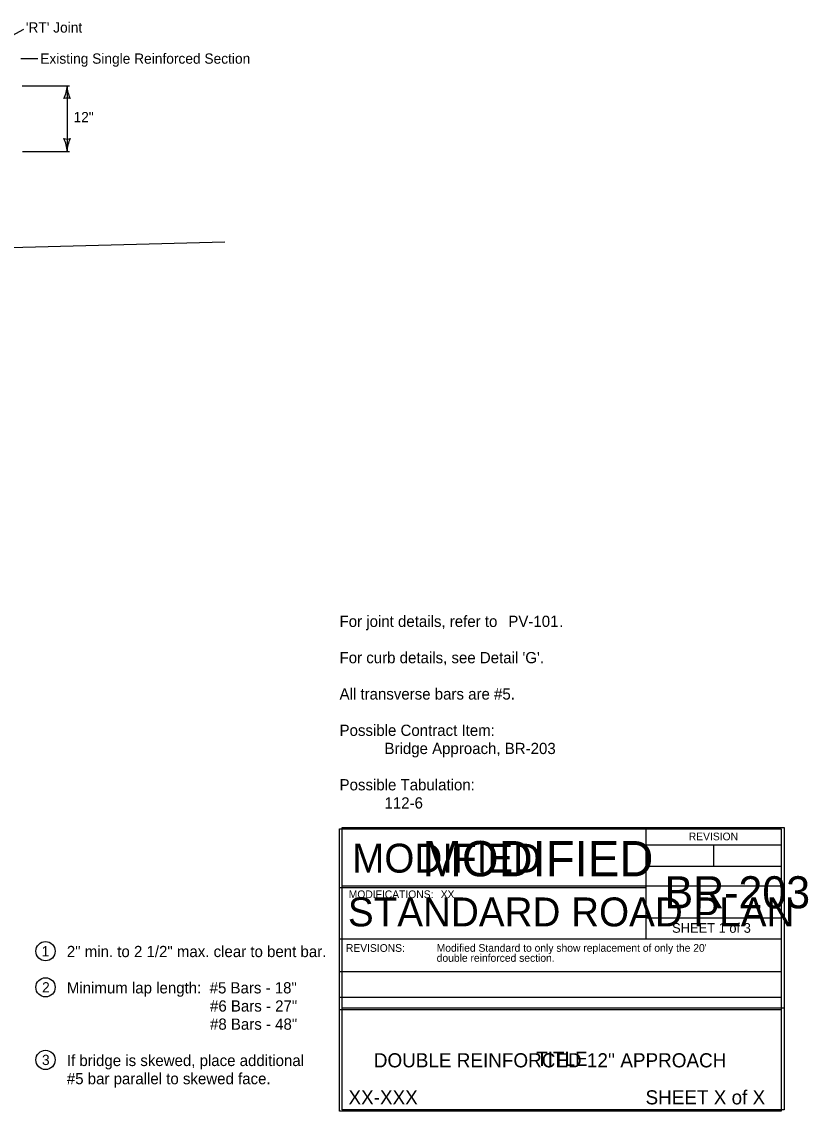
# Model space of a CAD drawing. Extents: x -2135039 to -2124495, y -2139046 to -2132546.
# Drawn here: x -2132982 to -2131757, y -2139046 to -2137348 of the extents above; entities that cross this region are included whole.
import ezdxf

# ---------------------------------------------------------------- set-up
doc = ezdxf.new("R2010")
doc.units = 0
for name, color, linetype in [('Barrier', 7, 'Continuous'), ('BridgeSuperStructureExisting', 7, 'Continuous'), ('Dimension', 7, 'Continuous'), ('dsnAlignmentCurveData', 7, 'Continuous'), ('dsnAlignmentTic', 7, 'Continuous'), ('DsnShtInsideBorder', 7, 'Continuous'), ('dsnStdLabel', 7, 'Continuous')]:
    doc.layers.add(name, color=color, linetype=linetype)

msp = doc.modelspace()

# ---------------------------------------------------------------- linework, layer by layer
at = {"layer": 'BridgeSuperStructureExisting'}
msp.add_line((-2132957.5, -2137405.9), (-2132984.1, -2137405.9), dxfattribs=at)
for centre in [(-2132945.4, -2138796.6), (-2132945.4, -2138852.9), (-2132945.4, -2138966)]:
    msp.add_circle(centre, 15, dxfattribs=at)
for centre, radius, start, end in [((-2132954.3, -2137448), 42.5, 331.9275, 360), ((-2132954.3, -2137448), 42.5, 331.9275, 360), ((-2132869.3, -2137448), 42.5, 180, 208.0725), ((-2132869.3, -2137448), 42.5, 180, 208.0725), ((-2132911.8, -2137483.6), 16.4, 72.2666, 107.7334), ((-2132911.8, -2137483.6), 16.4, 72.2666, 107.7334), ((-2132911.8, -2137514.7), 16.4, 252.2666, 287.7333), ((-2132954.3, -2137550.3), 42.5, 360, 28.0725), ((-2132869.3, -2137550.3), 42.5, 151.9275, 180)]:
    msp.add_arc(centre, radius, start, end, dxfattribs=at)
at = {"layer": 'Dimension'}
for p, q in [((-2132010.4, -2138605.9), (-2132010.4, -2138697.3)), ((-2132010.4, -2138630.9), (-2131799.4, -2138630.9)), ((-2131904.9, -2138630.9), (-2131904.9, -2138664.1)), ((-2132010.4, -2138664.1), (-2131799.4, -2138664.1)), ((-2132487.5, -2138697.3), (-2132010.4, -2138697.3)), ((-2132010.4, -2138697.3), (-2132010.4, -2138777.3)), ((-2131799.4, -2138745.1), (-2132010.4, -2138745.1)), ((-2132487.5, -2138777.3), (-2131799.4, -2138777.3)), ((-2132487.5, -2138828.3), (-2131799.4, -2138828.3)), ((-2132487.5, -2138868.3), (-2131799.4, -2138868.3)), ((-2132487.5, -2138887.3), (-2131799.4, -2138887.3))]:
    msp.add_line(p, q, dxfattribs=at)
msp.add_lwpolyline([(-2132487.5, -2138605.9), (-2131799.4, -2138605.9), (-2131799.4, -2139045.9), (-2132487.5, -2139045.9)], close=True, dxfattribs=at)
at = {"layer": 'DsnShtInsideBorder'}
for p, q in [((-2132483.1, -2138695), (-2131795.1, -2138695)), ((-2132483.1, -2138885), (-2131795.1, -2138885))]:
    msp.add_line(p, q, dxfattribs=at)
msp.add_lwpolyline([(-2132483.1, -2138603.7), (-2131795.1, -2138603.7), (-2131795.1, -2139043.7), (-2132483.1, -2139043.7)], close=True, dxfattribs=at)
at = {"layer": 'dsnStdLabel'}
for p, q in [((-2133142.6, -2137448), (-2132979.4, -2137359.7)), ((-2132981.9, -2137448), (-2132908, -2137448)), ((-2132911.8, -2137448), (-2132911.8, -2137550.3)), ((-2132981.4, -2137550.3), (-2132908, -2137550.3)), ((-2133760.8, -2137719.9), (-2132665.9, -2137691.3))]:
    msp.add_line(p, q, dxfattribs=at)

# ---------------------------------------------------------------- texts
at = {"layer": 'Barrier'}
for s, p in [('For joint details, refer to ', (-2132487.4, -2138291.3)), ('PV-101', (-2132224.5, -2138291.3)), ('PV-101', (-2132224.5, -2138291.3)), ('.', (-2132145.2, -2138291.3)), ("For curb details, see Detail 'G'.", (-2132487.4, -2138347.9)), ('All transverse bars are #5.', (-2132487.4, -2138404.5)), ('Possible Contract Item:', (-2132487.4, -2138461.1)), ('Bridge Approach, BR-203', (-2132417.4, -2138489.4)), ('Possible Tabulation:', (-2132487.4, -2138546)), ('112-6', (-2132417.4, -2138574.3)), ('112-6', (-2132417.4, -2138574.3)), ('2" min. to 2 1/2" max. clear to bent bar.', (-2132912.2, -2138805.8)), ('Minimum lap length:  #5 Bars - 18"', (-2132912.2, -2138862.4)), ('  #6 Bars - 27"', (-2132702.2, -2138890.7)), ('  #8 Bars - 48"', (-2132702.2, -2138919)), ('If bridge is skewed, place additional', (-2132912.2, -2138975.6)), ('#5 bar parallel to skewed face.', (-2132912.2, -2139003.9))]:
    msp.add_text(s, height=17.5, dxfattribs=at).set_placement(p)
at = {"layer": 'BridgeSuperStructureExisting'}
for s, p in [('1', (-2132951.4, -2138804.6)), ('2', (-2132950.8, -2138860.9)), ('3', (-2132950.9, -2138974))]:
    msp.add_text(s, height=16, dxfattribs=at).set_placement(p)
at = {"layer": 'Dimension'}
for s, height, p in [('REVISION', 12, (-2131943.4, -2138623.8)), ('BR-203', 50, (-2131981.2, -2138729.8)), ('STANDARD ROAD PLAN', 45.001, (-2132474.4, -2138757.9)), ('SHEET 1 of 3', 15, (-2131969.4, -2138767.9)), ("Modified Standard to only show replacement of only the 20' ", 12, (-2132336.1, -2138797.5)), ('double reinforced section.', 12, (-2132336.1, -2138813.1)), ("DOUBLE REINFORCED 12'' APPROACH", 22, (-2132434, -2138977.6))]:
    msp.add_text(s, height=height, dxfattribs=at).set_placement(p)
at = {"layer": 'dsnAlignmentCurveData'}
msp.add_text('REVISIONS:', height=12, dxfattribs=at).set_placement((-2132477.5, -2138797.6))
at = {"layer": 'dsnAlignmentTic'}
msp.add_text('MODIFIED', height=45, dxfattribs=at).set_placement((-2132467.8, -2138674.1))
at = {"layer": 'DsnShtInsideBorder'}
for s, height, p in [('MODIFIED', 55, (-2132358.1, -2138679.9)), ('MODIFICATIONS:', 12, (-2132473.1, -2138713.9)), ('XX', 12, (-2132329.9, -2138713.9)), ('TITLE', 22, (-2132181.1, -2138975.4)), ('XX-XXX', 22, (-2132473.5, -2139035.3)), ('SHEET X of X', 22, (-2132010.8, -2139035.3))]:
    msp.add_text(s, height=height, dxfattribs=at).set_placement(p)
at = {"layer": 'dsnStdLabel'}
for s, p in [("'RT' Joint", (-2132976.1, -2137365.2)), ('Existing Single Reinforced Section', (-2132953.6, -2137413.7)), ('12"', (-2132901.8, -2137504.9))]:
    msp.add_text(s, height=16, dxfattribs=at).set_placement(p)

doc.saveas('drawing.dxf')
